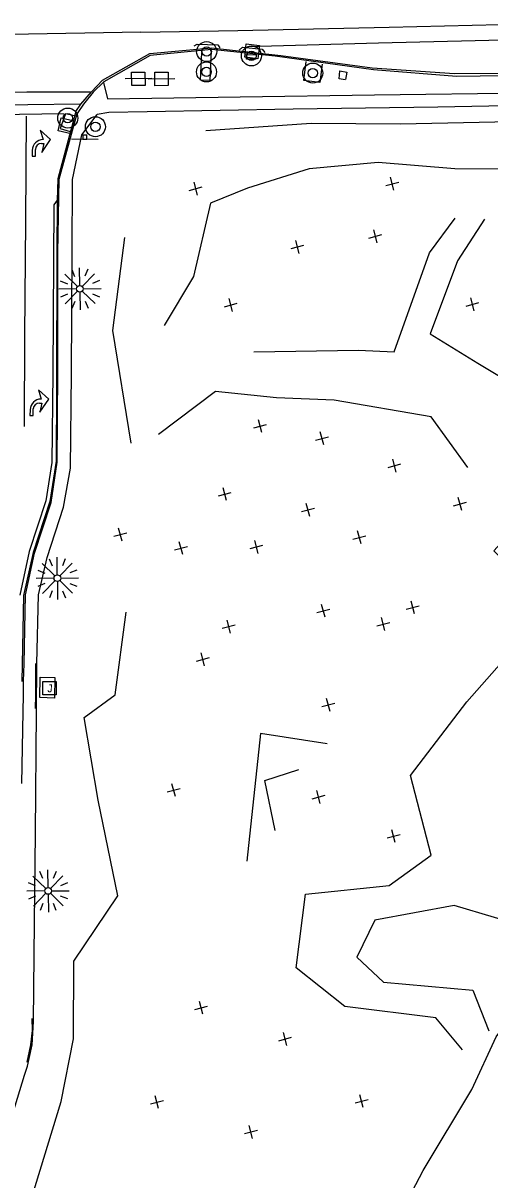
# Model space of a CAD drawing. Extents: x 4711259 to 4716401, y 890074 to 892728.
# Drawn here: x 4712586.5 to 4712761.3, y 890907.6 to 891341.1 of the extents above; entities that cross this region are included whole.
import ezdxf

# ---------------------------------------------------------------- set-up
doc = ezdxf.new("R2010")
doc.units = 0
for name, color, linetype in [('E_HY_STORM_Inlet', 7, 'Continuous'), ('E_HY_STORM_MH', 7, 'Continuous'), ('E_RDWY_ROAD_Curb', 7, 'Continuous'), ('E_RDWY_ROAD_EdgeConc', 7, 'Continuous'), ('E_RDWY_ROAD_Sidewalk', 7, 'Continuous'), ('E_RDWY_ROAD_Striping', 7, 'Continuous'), ('E_RDWY_ROAD_TBofCurb', 7, 'Continuous'), ('E_TERR_DTM_BrkLines', 7, 'Continuous'), ('E_TERR_DTM_RandomPt', 7, 'Continuous'), ('E_TRAF_ILLUM_Poles', 7, 'Continuous'), ('E_TRAF_SIGN_PublicSign', 7, 'Continuous'), ('E_UTIL_ELEC_GENERAL', 7, 'Continuous'), ('E_UTIL_ELEC_POLE', 7, 'Continuous')]:
    doc.layers.add(name, color=color, linetype=linetype)

msp = doc.modelspace()

# ---------------------------------------------------------------- linework, layer by layer
at = {"layer": 'E_HY_STORM_Inlet'}
for p, q in [((4712672.24, 891330.55), (4712672.24, 891330.55)), ((4712602.54, 891302.64), (4712602.54, 891302.64))]:
    msp.add_line(p, q, dxfattribs=at)
for points in [[(4712669.46, 891328.37), (4712670.06, 891333.33), (4712675.02, 891332.74), (4712674.42, 891327.77)], [(4712604.4, 891299.63), (4712599.53, 891300.77), (4712600.67, 891305.64), (4712605.54, 891304.5)]]:
    msp.add_lwpolyline(points, close=True, dxfattribs=at)
at = {"layer": 'E_HY_STORM_MH'}
for centre, radius in [((4712655.22, 891330.47), 3.75), ((4712655.22, 891330.47), 1.76), ((4712671.99, 891328.84), 3.75), ((4712671.99, 891328.84), 1.76), ((4712655.16, 891322.85), 3.75), ((4712655.16, 891322.85), 1.76), ((4712694.97, 891322.42), 3.75), ((4712694.97, 891322.42), 1.76), ((4712603.2, 891305.56), 3.75), ((4712603.2, 891305.56), 1.76), ((4712613.54, 891302.3), 3.75), ((4712613.54, 891302.3), 1.76)]:
    msp.add_circle(centre, radius, dxfattribs=at)
at = {"layer": 'E_RDWY_ROAD_Curb'}
for points in [[(4712606.27, 891307.97), (4712608.1, 891310.73), (4712612.05, 891315.34), (4712616.26, 891319.72), (4712633.88, 891329.8), (4712657.06, 891331.87), (4712683.06, 891328.98), (4712717.23, 891324.39), (4712748.09, 891322.2), (4712802.23, 891322.67)], [(4712606.27, 891307.97), (4712599.43, 891282.77), (4712599.16, 891274.81), (4712599.11, 891255.04), (4712598.98, 891204.46), (4712598.79, 891176.92), (4712596.46, 891161.78), (4712590.18, 891142.71), (4712586.6, 891126.6), (4712586.02, 891094.4)]]:
    msp.add_lwpolyline(points, dxfattribs=at)
at = {"layer": 'E_RDWY_ROAD_EdgeConc'}
for points in [[(4712650.51, 891332.56), (4712651.6, 891333.25), (4712659.45, 891333.03), (4712660.1, 891331.92)], [(4712656.57, 891330.88), (4712656.96, 891330.86), (4712656.4, 891319.62), (4712652.94, 891319.79), (4712653.45, 891330.13)], [(4712667.38, 891330.96), (4712668.59, 891332.06), (4712676.07, 891331.42), (4712676.99, 891330.1)], [(4712698.54, 891325.78), (4712697.65, 891318.9), (4712691.62, 891319.68), (4712692.54, 891326.75)], [(4712707.15, 891319.91), (4712704.84, 891320.22), (4712705.16, 891323.27), (4712707.71, 891322.8), (4712707.24, 891319.94)], [(4712605.66, 891306.34), (4712602.29, 891307.17), (4712600.39, 891301.59), (4712604.05, 891300.47)], [(4712599.16, 891274.81), (4712597.94, 891273.07), (4712597.53, 891209.98), (4712597.25, 891176.42), (4712595.02, 891162.12), (4712588.68, 891143.07), (4712585.28, 891126.75)]]:
    msp.add_lwpolyline(points, dxfattribs=at)
for points in [[(4712673.73, 891329.23), (4712673.68, 891327.57), (4712670.13, 891327.67), (4712670.17, 891329.33)], [(4712592.68, 891088.32), (4712592.89, 891095.97), (4712598.38, 891095.81), (4712598.16, 891088.16)]]:
    msp.add_lwpolyline(points, close=True, dxfattribs=at)
at = {"layer": 'E_RDWY_ROAD_Sidewalk'}
for points in [[(4712616.62, 891318.93), (4712618.04, 891312.75), (4712667.79, 891313.47), (4712718.04, 891314.23), (4712775.86, 891315.03), (4712782.91, 891315.08), (4712827.5, 891316.13), (4712870.43, 891316.75), (4712906, 891317.33), (4712930.74, 891314.59), (4712942.34, 891308.51), (4712941.4, 891316.03)], [(4712547.71, 891314.89), (4712587.86, 891315.33), (4712611.53, 891315.44)], [(4712906.74, 891312.11), (4712852.75, 891311.57), (4712805.37, 891310.82), (4712741.81, 891309.69), (4712687.67, 891308.84), (4712632.95, 891307.86), (4712618.52, 891307.62), (4712614.22, 891306.88)], [(4712607.78, 891310.71), (4712588.27, 891310.51), (4712551.65, 891309.83)], [(4712579.07, 890920.88), (4712587.01, 890946.82), (4712588.09, 890950.14), (4712589.9, 890958.2), (4712590.41, 890966.92), (4712590.72, 891004.02), (4712591.07, 891037.5), (4712591.51, 891082.96), (4712591.57, 891101.1), (4712592.24, 891126.89), (4712595.48, 891140.87), (4712601.61, 891159.66), (4712604.23, 891174.28), (4712604.53, 891209.82), (4712604.83, 891255.06), (4712605.01, 891282.54), (4712608.4, 891299.26), (4712614.22, 891306.88)]]:
    msp.add_lwpolyline(points, dxfattribs=at)
at = {"layer": 'E_RDWY_ROAD_Striping'}
for p, q in [((4712596.78, 891297.52), (4712592.84, 891301)), ((4712592.84, 891301), (4712593.92, 891297.52)), ((4712593.34, 891296), (4712594.2, 891296)), ((4712593.53, 891292.62), (4712596.78, 891297.52)), ((4712594.2, 891296), (4712593.53, 891292.62)), ((4712589.91, 891293.44), (4712589.9, 891291.25)), ((4712589.9, 891291.25), (4712591.04, 891291.25)), ((4712591.04, 891291.25), (4712591.05, 891293.72)), ((4712596.05, 891200.16), (4712592.2, 891203.73)), ((4712592.2, 891203.73), (4712593.19, 891200.23)), ((4712592.58, 891198.73), (4712593.44, 891198.7)), ((4712592.69, 891195.34), (4712596.05, 891200.16)), ((4712593.44, 891198.7), (4712592.69, 891195.34)), ((4712589.09, 891196.24), (4712589.03, 891194.05)), ((4712590.17, 891194.02), (4712590.24, 891196.5)), ((4712589.03, 891194.05), (4712590.17, 891194.02))]:
    msp.add_line(p, q, dxfattribs=at)
for points in [[(4712630.55, 891337.79), (4712666.87, 891338.35)], [(4712666.87, 891338.35), (4712723.53, 891339.58), (4712785.72, 891341.13)], [(4712792.06, 891335.4), (4712719.64, 891333.6), (4712670.64, 891332.24)], [(4712576.61, 891306.83), (4712601.89, 891307.32)], [(4712587.59, 891306.22), (4712587.31, 891266.94), (4712586.93, 891224.05), (4712586.81, 891189.99)]]:
    msp.add_lwpolyline(points, dxfattribs=at)
for centre, radius, start, end in [((4712594, 891293.43), 4.1, 91.1653, 179.833), ((4712593.34, 891293.72), 2.29, 89.8425, 179.8365), ((4712593.18, 891196.14), 4.1, 89.8387, 178.5065), ((4712592.52, 891196.44), 2.29, 88.5159, 178.5099)]:
    msp.add_arc(centre, radius, start, end, dxfattribs=at)
at = {"layer": 'E_RDWY_ROAD_TBofCurb'}
for points in [[(4712953.07, 891303.51), (4712949.47, 891309.05), (4712945.69, 891313.06), (4712941.39, 891316.26), (4712914.02, 891323.69), (4712856.11, 891322.69), (4712802.29, 891321.89), (4712748.87, 891321.18), (4712717.78, 891323.58), (4712680.9, 891328.69), (4712657, 891331.2), (4712634.03, 891329.01), (4712616.68, 891319.17), (4712612.67, 891315.29), (4712609.14, 891310.78), (4712606.67, 891307.21)], [(4712586.02, 891056.17), (4712586.47, 891083.01), (4712586.59, 891089.41), (4712586.55, 891094.47), (4712586.81, 891101.02), (4712587.3, 891126.84), (4712590.78, 891142.42), (4712596.93, 891161.4), (4712599.21, 891176.61), (4712599.46, 891209.94), (4712599.42, 891255.06), (4712600.02, 891282.62), (4712606.67, 891307.21)]]:
    msp.add_lwpolyline(points, dxfattribs=at)
at = {"layer": 'E_TERR_DTM_BrkLines'}
for points in [[(4712630.55, 891337.79), (4712581.52, 891336.86), (4712530.23, 891336.15), (4712505.32, 891336.16)], [(4712654.89, 891300.91), (4712694.33, 891303.58), (4712727.8, 891303.34), (4712780.86, 891304.54), (4712827.05, 891306.5), (4712840.53, 891305.3)], [(4712818.87, 891288.88), (4712795.3, 891287.02), (4712772.12, 891286.41), (4712748.21, 891286.57), (4712719.46, 891288.9), (4712693.6, 891286.51), (4712670.57, 891279.21), (4712656.65, 891273.7), (4712650.25, 891246.16), (4712639.27, 891227.82)], [(4712672.92, 891217.92), (4712712.05, 891218.56), (4712725.48, 891217.89), (4712738.66, 891254.99), (4712748.33, 891268.07)], [(4712759.31, 891267.7), (4712749.14, 891252.08), (4712738.91, 891224.68), (4712756.76, 891213.67), (4712782.71, 891198.22)], [(4712626.99, 891183.75), (4712620.01, 891225.96), (4712624.59, 891260.72)], [(4712753.04, 891174.56), (4712739.27, 891193.54), (4712702.94, 891199.76), (4712681.36, 891200.63), (4712658.47, 891203.06), (4712637.22, 891187)], [(4712751.02, 890956.25), (4712741.05, 890968.24), (4712707, 890972.57), (4712688.73, 890987.02), (4712692.2, 891014.68), (4712723.62, 891017.88), (4712739.37, 891029.29), (4712731.52, 891059.09), (4712752.68, 891086.69), (4712777.06, 891114.39), (4712778.49, 891127.76), (4712762.84, 891143.32), (4712770.23, 891151.55), (4712768.43, 891164.71), (4712795.27, 891158.9), (4712802.24, 891156.78), (4712820.97, 891175.47)], [(4712584.57, 890877.72), (4712633.89, 890864.36), (4712668.9, 890849.64), (4712691.68, 890844.86), (4712716.66, 890873.62), (4712736.29, 890911.04), (4712754.62, 890941.49), (4712763.63, 890961.15), (4712779.84, 890982.78), (4712788.58, 890993.18), (4712796.25, 891016.65), (4712815.64, 891044.82), (4712833.35, 891078.42), (4712846.86, 891110.24), (4712854.23, 891131.92)], [(4712720.27, 890847.58), (4712707.71, 890834.36), (4712687.49, 890827.69), (4712648.52, 890844.93), (4712603.85, 890861.8), (4712579.95, 890870.72), (4712580.64, 890887.85), (4712589.6, 890900.52), (4712600.72, 890936.99), (4712605.28, 890960.48), (4712605.41, 890989.48), (4712621.97, 891013.96), (4712614.63, 891049.82), (4712609.32, 891080.82), (4712620.89, 891089.34), (4712625.01, 891120.29)], [(4712591.12, 891101.06), (4712591.11, 891094.39), (4712591.1, 891089.07), (4712590.98, 891084.29)], [(4712700.4, 891071.02), (4712675.42, 891074.87), (4712670.32, 891027.07)], [(4712680.86, 891038.5), (4712677.06, 891057.27), (4712689.78, 891061.32)], [(4712778.13, 891001.44), (4712747.88, 891010.4), (4712718.16, 891004.86), (4712711.51, 890991), (4712721.48, 890981.63), (4712754.9, 890978.64), (4712760.97, 890963.38)], [(4712589.76, 890968.06), (4712589.84, 890963.59), (4712589.21, 890958.19), (4712587.83, 890951.63)]]:
    msp.add_lwpolyline(points, dxfattribs=at)
at = {"layer": 'E_TERR_DTM_RandomPt'}
for p, q in [((4712651.77, 891276.67), (4712650.49, 891281.5)), ((4712722.33, 891280.31), (4712727.17, 891281.58)), ((4712725.38, 891278.53), (4712724.11, 891283.37)), ((4712648.71, 891278.45), (4712653.55, 891279.72)), ((4712689.88, 891254.83), (4712688.61, 891259.66)), ((4712716.03, 891260.57), (4712720.86, 891261.86)), ((4712719.09, 891258.8), (4712717.8, 891263.63)), ((4712686.83, 891256.61), (4712691.67, 891257.88)), ((4712664.9, 891233.07), (4712663.61, 891237.9)), ((4712755.46, 891233.3), (4712754.16, 891238.13)), ((4712661.84, 891234.84), (4712666.67, 891236.13)), ((4712752.39, 891235.06), (4712757.22, 891236.36)), ((4712672.84, 891189.41), (4712677.67, 891190.7)), ((4712675.9, 891187.64), (4712674.61, 891192.47)), ((4712696.02, 891184.81), (4712700.85, 891186.11)), ((4712699.08, 891183.05), (4712697.79, 891187.88)), ((4712726.23, 891172.86), (4712724.93, 891177.69)), ((4712723.16, 891174.63), (4712727.99, 891175.92)), ((4712659.6, 891163.92), (4712664.43, 891165.22)), ((4712662.66, 891162.16), (4712661.37, 891166.99)), ((4712693.81, 891156.25), (4712692.54, 891161.08)), ((4712747.7, 891160.25), (4712752.53, 891161.55)), ((4712750.77, 891158.49), (4712749.47, 891163.32)), ((4712690.76, 891158.03), (4712695.59, 891159.3)), ((4712623.51, 891147.01), (4712622.23, 891151.84)), ((4712620.45, 891148.79), (4712625.29, 891150.06)), ((4712646.28, 891141.92), (4712644.98, 891146.75)), ((4712674.53, 891142.38), (4712673.26, 891147.22)), ((4712710.01, 891147.72), (4712714.84, 891149.02)), ((4712713.07, 891145.95), (4712711.77, 891150.78)), ((4712643.22, 891143.69), (4712648.05, 891144.98)), ((4712671.47, 891144.17), (4712676.31, 891145.44)), ((4712696.5, 891120.19), (4712701.33, 891121.49)), ((4712699.56, 891118.42), (4712698.27, 891123.25)), ((4712730.01, 891121.46), (4712734.85, 891122.73)), ((4712733.07, 891119.68), (4712731.8, 891124.51)), ((4712664.12, 891112.53), (4712662.85, 891117.37)), ((4712718.95, 891115.26), (4712723.79, 891116.53)), ((4712722, 891113.48), (4712720.73, 891118.31)), ((4712661.07, 891114.32), (4712665.91, 891115.59)), ((4712651.42, 891102.04), (4712656.26, 891103.31)), ((4712654.47, 891100.26), (4712653.2, 891105.09)), ((4712698.38, 891084.94), (4712703.21, 891086.22)), ((4712701.43, 891083.16), (4712700.16, 891088)), ((4712643.49, 891051.21), (4712642.22, 891056.05)), ((4712640.44, 891052.99), (4712645.28, 891054.27)), ((4712694.73, 891050.41), (4712699.56, 891051.71)), ((4712697.79, 891048.64), (4712696.49, 891053.47)), ((4712725.89, 891033.98), (4712724.6, 891038.81)), ((4712722.83, 891035.75), (4712727.66, 891037.04)), ((4712653.81, 890969.64), (4712652.53, 890974.47)), ((4712650.75, 890971.42), (4712655.59, 890972.69)), ((4712682.23, 890959.72), (4712687.06, 890961.02)), ((4712685.29, 890957.95), (4712684, 890962.78)), ((4712637.21, 890934.27), (4712635.94, 890939.11)), ((4712713.89, 890934.65), (4712712.62, 890939.49)), ((4712634.16, 890936.05), (4712638.99, 890937.32)), ((4712710.84, 890936.44), (4712715.67, 890937.71)), ((4712669.4, 890924.88), (4712674.24, 890926.16)), ((4712672.45, 890923.1), (4712671.18, 890927.94))]:
    msp.add_line(p, q, dxfattribs=at)
at = {"layer": 'E_TRAF_ILLUM_Poles'}
for p, q in [((4712606.84, 891242.42), (4712602.07, 891247.08)), ((4712604.66, 891248.84), (4712605.76, 891246.21)), ((4712607.72, 891242.8), (4712607.64, 891249.46)), ((4712608.6, 891242.44), (4712613.26, 891247.21)), ((4712610.71, 891248.88), (4712609.64, 891246.24)), ((4712600.4, 891244.53), (4712603.03, 891243.46)), ((4712615.03, 891244.62), (4712612.4, 891243.51)), ((4712606.48, 891241.53), (4712599.81, 891241.45)), ((4712603.06, 891239.58), (4712600.44, 891238.47)), ((4712606.86, 891240.65), (4712602.2, 891235.88)), ((4712607.75, 891240.3), (4712607.83, 891233.63)), ((4712608.63, 891240.67), (4712613.4, 891236.02)), ((4712608.98, 891241.56), (4712615.65, 891241.64)), ((4712612.43, 891239.63), (4712615.06, 891238.56)), ((4712605.82, 891236.85), (4712604.75, 891234.21)), ((4712609.7, 891236.88), (4712610.81, 891234.25)), ((4712598.39, 891133.93), (4712593.62, 891138.59)), ((4712596.21, 891140.36), (4712597.31, 891137.73)), ((4712599.27, 891134.31), (4712599.19, 891140.98)), ((4712600.16, 891133.96), (4712604.81, 891138.73)), ((4712602.27, 891140.39), (4712601.19, 891137.76)), ((4712591.95, 891136.05), (4712594.59, 891134.97)), ((4712606.58, 891136.14), (4712603.95, 891135.03)), ((4712598.03, 891133.05), (4712591.37, 891132.97)), ((4712594.61, 891131.09), (4712591.99, 891129.99)), ((4712598.41, 891132.17), (4712593.75, 891127.4)), ((4712599.3, 891131.81), (4712599.38, 891125.15)), ((4712600.18, 891132.19), (4712604.95, 891127.53)), ((4712600.53, 891133.08), (4712607.2, 891133.16)), ((4712603.98, 891131.15), (4712606.61, 891130.08)), ((4712597.37, 891128.36), (4712596.3, 891125.73)), ((4712601.25, 891128.39), (4712602.36, 891125.77)), ((4712594.92, 891016.73), (4712590.15, 891021.38)), ((4712593.85, 891020.52), (4712592.74, 891023.15)), ((4712595.8, 891017.1), (4712595.72, 891023.77)), ((4712596.69, 891016.75), (4712601.35, 891021.52)), ((4712598.8, 891023.19), (4712597.73, 891020.55)), ((4712591.12, 891017.76), (4712588.48, 891018.84)), ((4712603.11, 891018.93), (4712600.48, 891017.82)), ((4712594.57, 891015.84), (4712587.9, 891015.76)), ((4712591.15, 891013.89), (4712588.52, 891012.78)), ((4712594.94, 891014.96), (4712590.29, 891010.19)), ((4712595.83, 891014.6), (4712595.91, 891007.94)), ((4712596.71, 891014.98), (4712601.48, 891010.32)), ((4712597.07, 891015.87), (4712603.73, 891015.95)), ((4712603.15, 891012.87), (4712600.51, 891013.94)), ((4712593.9, 891011.16), (4712592.83, 891008.52)), ((4712598.89, 891008.56), (4712597.78, 891011.19))]:
    msp.add_line(p, q, dxfattribs=at)
for centre in [(4712607.73, 891241.55), (4712599.28, 891133.06), (4712595.82, 891015.85)]:
    msp.add_circle(centre, 1.25, dxfattribs=at)
at = {"layer": 'E_TRAF_SIGN_PublicSign'}
for p, q in [((4712614.59, 891297.54), (4712604.59, 891297.67)), ((4712609.6, 891298.35), (4712609.6, 891298.35))]:
    msp.add_line(p, q, dxfattribs=at)
msp.add_lwpolyline([(4712610.34, 891297.59), (4712610.36, 891299.09), (4712608.86, 891299.11), (4712608.84, 891297.61)], close=True, dxfattribs=at)
at = {"layer": 'E_UTIL_ELEC_GENERAL'}
msp.add_lwpolyline([(4712598.84, 891089.37), (4712593.84, 891089.4), (4712593.87, 891094.4), (4712598.87, 891094.37)], close=True, dxfattribs=at)
at = {"layer": 'E_UTIL_ELEC_POLE'}
for p, q in [((4712634.63, 891320.33), (4712624.63, 891320.21)), ((4712643.29, 891320.28), (4712633.29, 891320.16))]:
    msp.add_line(p, q, dxfattribs=at)
for points in [[(4712632.16, 891317.8), (4712627.16, 891317.74), (4712627.1, 891322.74), (4712632.1, 891322.8)], [(4712640.82, 891317.75), (4712635.82, 891317.69), (4712635.76, 891322.69), (4712640.76, 891322.75)]]:
    msp.add_lwpolyline(points, close=True, dxfattribs=at)

# ---------------------------------------------------------------- texts
at = {"layer": 'E_UTIL_ELEC_GENERAL'}
msp.add_text('J', height=3, rotation=359.7251, dxfattribs=at).set_placement((4712595.5, 891090.32))

doc.saveas('drawing.dxf')
